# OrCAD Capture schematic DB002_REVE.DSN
size B
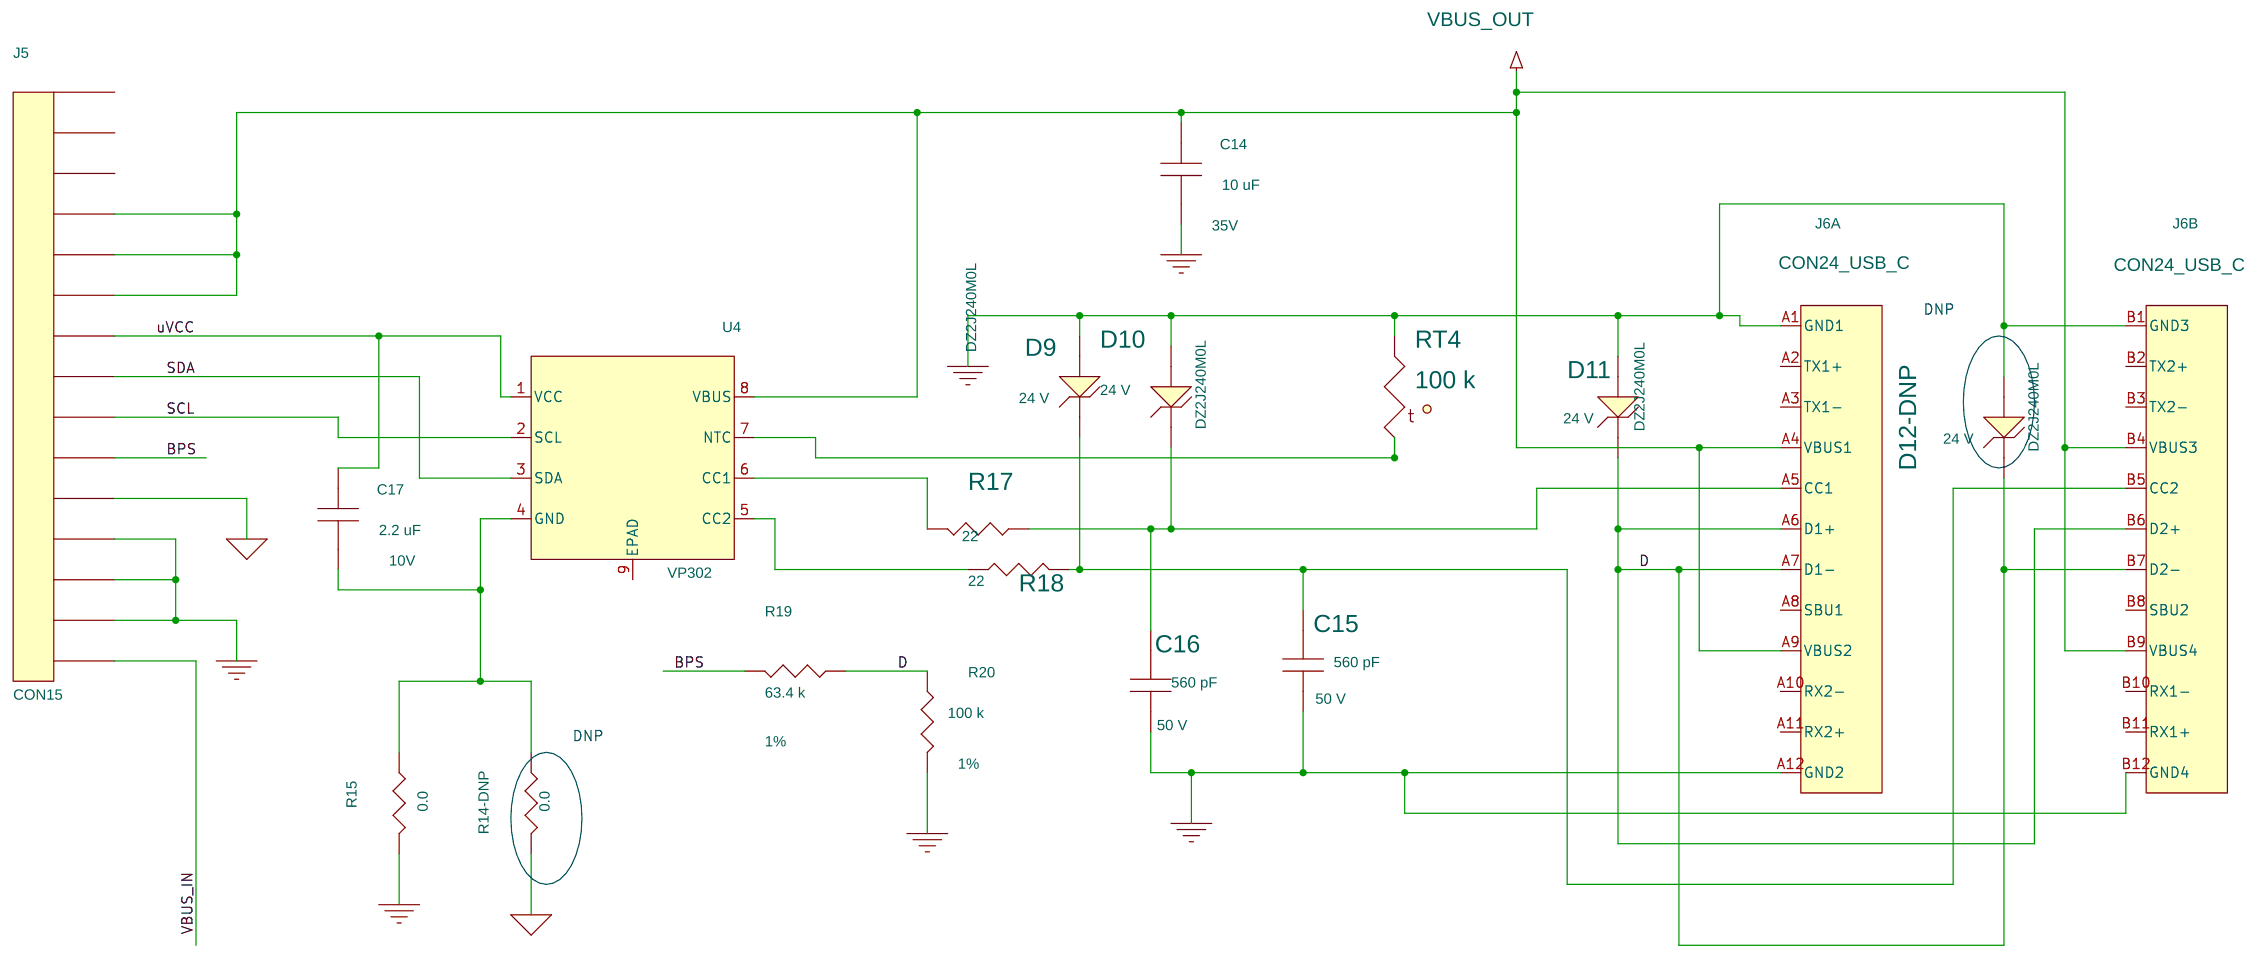
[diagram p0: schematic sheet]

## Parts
C14  10 uF  [pismc1210]
C15  560 pF  [pismc0603]
C16  560 pF  [pismc0603]
C17  2.2 uF  [pismc0603]
D9  DZ2J240M0L  [pi_sm_d_ssmini2p]
D10  DZ2J240M0L  [pi_sm_d_ssmini2p]
D11  DZ2J240M0L  [pi_sm_d_ssmini2p]
D12-DNP  DZ2J240M0L  [pi_sm_d_ssmini2p]
J5  CON15  [pi_unshroud_2mm_15pra]
J6  CON24_USB_C  [pi_conn_USBC_Wurth]  (sections A,B)
R14-DNP  0.0  [pismr0603]
R15  0.0  [pismr0603]
R17  22  [pismr0603]
R18  22  [pismr0603]
R19  63.4 k  [pismr0603]
R20  100 k  [pismr0603]
RT4  100 k  [pismr0603]
U4  VP302  [PI_SM_DFN-8]

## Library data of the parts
C14 = CAP_NP: Disp_Voltage: 35V; Part Number: 20-00792-00; ROOM: 3; Voltage: 35 V
C15 C16 = CAP_NP: Disp_Voltage: 50 V; Part Number: 20-08982-00; ROOM: 3; Voltage: 50 V
C17 = CAP_NP: Disp_Voltage: 10V; Part Number: 20-00983-00; Voltage: 10 V
D9-D11 D12-DNP = DIODE_ZENER: Disp_Voltage: 24 V; Part Number: 15-01042-00; ROOM: 3
J5 = CON15: Part Number: 35-00429-00; ROOM: 3
J6 = CON24_USB: Part Number: 35-00414-00; ROOM: 3
R14-DNP R15 = R: Part Number: 05-03158-00
R17 R18 = R: COMPGROUP: 1; Part Number: 05-01648-00; ROOM: 3
R19 = R: Disp_Tol: 1%; Part Number: 05-03261-00
R20 = R: Disp_Tol: 1%; Part Number: 05-01174-00
RT4 = THERMISTOR: Part Number: 90-00063-00; ROOM: 3
U4 = VP302: Part Number: 45-00495-00; ROOM: 3

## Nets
GND: C14.2 C15.1 C16.1 D9.2 D10.2 D11.2 D12-DNP.2 J5.2 J5.3 J5.4 J6.A1(GND1) J6.A12(GND2) J6.B1(GND3) J6.B12(GND4) R15.2 R20.2 RT4.1
GND_SIGNAL: J5.5 R14-DNP.2
VBUS_IN: J5.1
VBUS_OUT: C14.1 J5.10 J5.11 J5.12 J6.A4(VBUS1) J6.A9(VBUS2) J6.B4(VBUS3) J6.B9(VBUS4) U4.8(VBUS)
BPS: J5.6 R19.2
D: D11.1 D12-DNP.1 J6.A6(D1+) J6.A7(D1-) J6.B6(D2+) J6.B7(D2-) R19.1 R20.1
SCL: J5.7 U4.2(SCL)
SDA: J5.8 U4.3(SDA)
uVCC: C17.1 J5.9 U4.1(VCC)
N12100170: C15.2 D9.1 J6.B5(CC2) R18.1
N12100174: C16.2 D10.1 J6.A5(CC1) R17.2
N12100230: RT4.2 U4.7(NTC)
N12102267: C17.2 R14-DNP.1 R15.1 U4.4(GND)
N12102285: R17.1 U4.6(CC1)
N12102289: R18.2 U4.5(CC2)

Not connected (* = marked no-connect by the designer): J5 13 14 15; J6 A2(TX1+) A3(TX1-) A8(SBU1) A10(RX2-) A11(RX2+) B2(TX2+) B3(TX2-) B8(SBU2) B10(RX1-) B11(RX1+); U4 9(EPAD)

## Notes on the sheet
- DNP
- DNP
